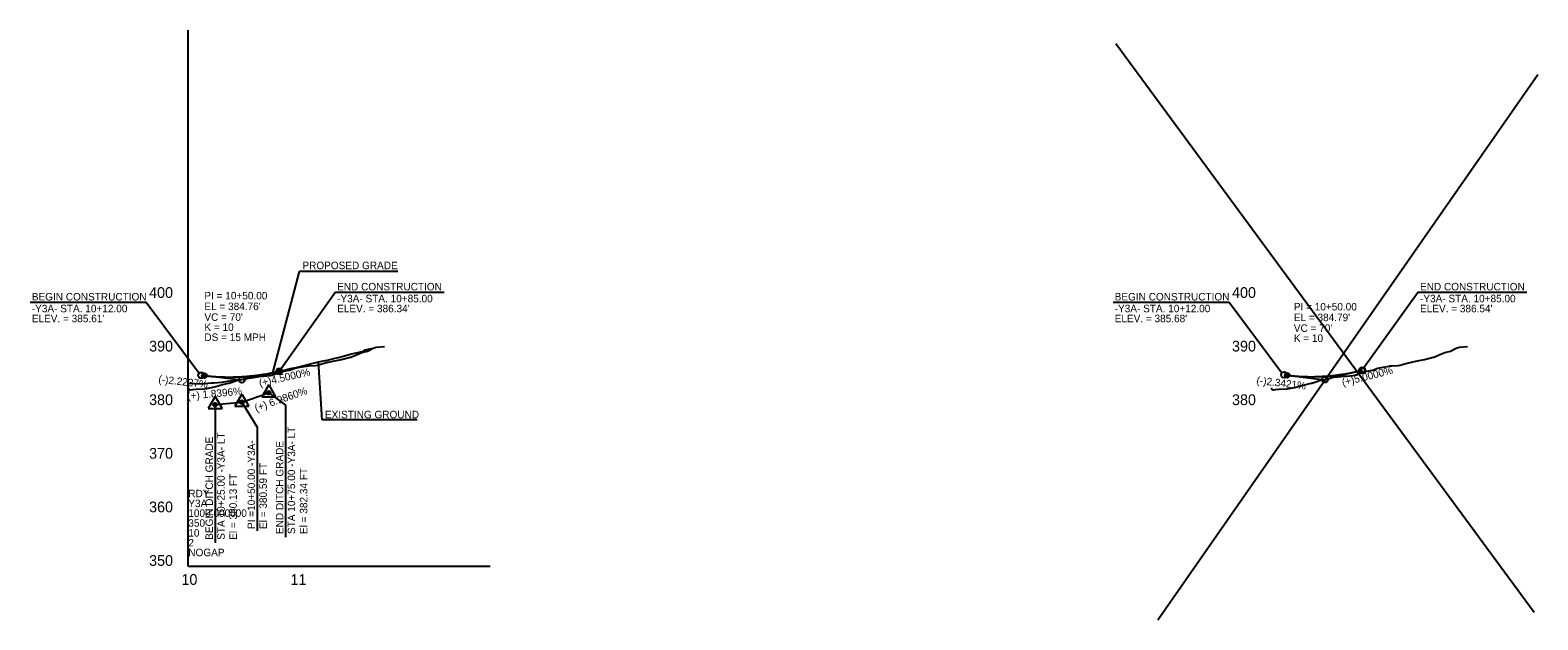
# Model space of a CAD drawing. Extents: x 1625686 to 1640492, y 1161393 to 1175642.
# Drawn here: x 1630069 to 1631477, y 1163675 to 1164225 of the extents above; entities that cross this region are included whole.
import ezdxf

# ---------------------------------------------------------------- set-up
doc = ezdxf.new("R2010")
doc.units = 0
for name, color, linetype in [('Exist Profile Cell', 7, 'Continuous'), ('Exist Vertical Profile Ground Line', 7, 'Continuous'), ('Exist Vertical Profile Horizontal Axis Label Major', 7, 'Continuous'), ('Exist Vertical Profile Vertical Axis Label', 7, 'Continuous'), ('Prop Vertical Profile Curve Label', 7, 'Continuous'), ('Prop Vertical Profile Ditch Grade Left', 7, 'Continuous'), ('Prop Vertical Profile Ditch Grade Left Label', 7, 'Continuous'), ('Prop Vertical Profile Grade', 7, 'Continuous'), ('Prop Vertical Profile Grade Label', 7, 'Continuous'), ('Prop VPI Ditch Grade Left Label', 7, 'Continuous'), ('Prop VPI Label', 7, 'Continuous'), ('Scratch_Level_1', 7, 'Continuous'), ('Scratch_Level_3', 7, 'Continuous')]:
    doc.layers.add(name, color=color, linetype=linetype)

msp = doc.modelspace()

# ---------------------------------------------------------------- linework, layer by layer
at = {"layer": 'Exist Profile Cell'}
for q in [(1630217, 1164224.9), (1630498.6, 1163724.9), (1630217, 1163724.9)]:
    msp.add_line((1630217, 1163724.9), q, dxfattribs=at)
at = {"layer": 'Exist Vertical Profile Ground Line'}
for points in [[(1630217, 1163895.6), (1630228, 1163894.9), (1630238.6, 1163895.8), (1630240.9, 1163895.9), (1630248.5, 1163896.4), (1630253.5, 1163897.3), (1630265.9, 1163899.1), (1630277.8, 1163900.9), (1630281.5, 1163901.5), (1630282.8, 1163901.8), (1630287.5, 1163902.9), (1630300.4, 1163906.2), (1630312.4, 1163909.1), (1630317.8, 1163910.3), (1630320.3, 1163910.9), (1630338.6, 1163915.5), (1630344.8, 1163916.6), (1630345.9, 1163916.7), (1630347.7, 1163917.2), (1630355.4, 1163919.2), (1630357.3, 1163919.6), (1630369.4, 1163922.8), (1630378, 1163924.9), (1630380.5, 1163925.5), (1630382.2, 1163926.6), (1630389.5, 1163928.1), (1630392.3, 1163929), (1630400.2, 1163929.7)], [(1631227.8, 1163891.3), (1631229, 1163889.4), (1631229.8, 1163889.3), (1631231.9, 1163889.7), (1631234.8, 1163890.1), (1631243, 1163890.4), (1631249.4, 1163891.6), (1631254.6, 1163892.8), (1631257.5, 1163893.7), (1631265, 1163895.6), (1631265.6, 1163895.7), (1631267.7, 1163896.3), (1631273.7, 1163898.3), (1631275.4, 1163898.3), (1631281.8, 1163899.8), (1631285.8, 1163901.2), (1631289.9, 1163901.6), (1631296.2, 1163902.1), (1631298, 1163902.1), (1631304, 1163902.8), (1631306.1, 1163903), (1631306.6, 1163903.2), (1631314.2, 1163905.7), (1631317, 1163906.7), (1631322.2, 1163907.8), (1631327.4, 1163909.5), (1631330.3, 1163910.1), (1631337.8, 1163911.5), (1631338.4, 1163911.6), (1631340.4, 1163911.7), (1631346.5, 1163912.1), (1631348.3, 1163912.5), (1631354.6, 1163914.3), (1631358.7, 1163915), (1631362.7, 1163916.1), (1631369.1, 1163917.4), (1631370.8, 1163917.6), (1631376.7, 1163919.1), (1631378.9, 1163919.7), (1631379.5, 1163919.9), (1631386.9, 1163923), (1631389.9, 1163924.1), (1631395, 1163925.5), (1631400.3, 1163928.1), (1631403.1, 1163929), (1631410.9, 1163929.7)]]:
    msp.add_lwpolyline(points, dxfattribs=at)
at = {"layer": 'Prop Vertical Profile Curve Label'}
for centre in [(1630302, 1163906.6), (1631312.8, 1163907.6), (1630232, 1163902.6), (1631242.8, 1163902.9)]:
    msp.add_circle(centre, 2.25, dxfattribs=at)
at = {"layer": 'Prop Vertical Profile Ditch Grade Left'}
msp.add_lwpolyline([(1630242, 1163875.5), (1630267, 1163877.8), (1630292, 1163886.6)], dxfattribs=at)
at = {"layer": 'Prop Vertical Profile Grade'}
for p, q in [((1630229, 1163902.9), (1630232, 1163902.6)), ((1631239.8, 1163903.3), (1631242.8, 1163902.9))]:
    msp.add_line(p, q, dxfattribs=at)
for points in [[(1630232, 1163902.6), (1630233.4, 1163902.4), (1630234.8, 1163902.3), (1630236.2, 1163902.2), (1630237.6, 1163902), (1630239, 1163901.9), (1630240.4, 1163901.8), (1630241.8, 1163901.7), (1630243.2, 1163901.6), (1630244.6, 1163901.6), (1630246, 1163901.5), (1630247.4, 1163901.5), (1630248.8, 1163901.4), (1630250.2, 1163901.4), (1630251.6, 1163901.3), (1630253, 1163901.3), (1630254.4, 1163901.3), (1630255.8, 1163901.3), (1630257.2, 1163901.3), (1630258.6, 1163901.3), (1630260, 1163901.4), (1630261.4, 1163901.4), (1630262.8, 1163901.4), (1630264.2, 1163901.5), (1630265.6, 1163901.6), (1630267, 1163901.6), (1630268.4, 1163901.7), (1630269.8, 1163901.8), (1630271.2, 1163901.9), (1630272.6, 1163902), (1630274, 1163902.2), (1630275.4, 1163902.3), (1630276.8, 1163902.4), (1630278.2, 1163902.6), (1630279.6, 1163902.7), (1630281, 1163902.9), (1630282.4, 1163903.1), (1630283.8, 1163903.3), (1630285.2, 1163903.5), (1630286.6, 1163903.7), (1630288, 1163903.9), (1630289.4, 1163904.1), (1630290.8, 1163904.4), (1630292.2, 1163904.6), (1630293.6, 1163904.9), (1630295, 1163905.1), (1630296.4, 1163905.4), (1630297.8, 1163905.7), (1630299.2, 1163906), (1630300.6, 1163906.3), (1630302, 1163906.6)], [(1631242.8, 1163902.9), (1631244.2, 1163902.8), (1631245.6, 1163902.6), (1631247, 1163902.5), (1631248.4, 1163902.4), (1631249.8, 1163902.2), (1631251.2, 1163902.1), (1631252.6, 1163902), (1631254, 1163901.9), (1631255.4, 1163901.9), (1631256.8, 1163901.8), (1631258.2, 1163901.7), (1631259.6, 1163901.7), (1631261, 1163901.7), (1631262.4, 1163901.6), (1631263.8, 1163901.6), (1631265.2, 1163901.6), (1631266.6, 1163901.6), (1631268, 1163901.6), (1631269.4, 1163901.7), (1631270.8, 1163901.7), (1631272.2, 1163901.7), (1631273.6, 1163901.8), (1631275, 1163901.9), (1631276.4, 1163902), (1631277.8, 1163902), (1631279.2, 1163902.1), (1631280.6, 1163902.2), (1631282, 1163902.4), (1631283.4, 1163902.5), (1631284.8, 1163902.6), (1631286.2, 1163902.8), (1631287.6, 1163902.9), (1631289, 1163903.1), (1631290.4, 1163903.3), (1631291.8, 1163903.5), (1631293.2, 1163903.7), (1631294.6, 1163903.9), (1631296, 1163904.1), (1631297.4, 1163904.3), (1631298.8, 1163904.6), (1631300.2, 1163904.8), (1631301.6, 1163905.1), (1631303, 1163905.4), (1631304.4, 1163905.7), (1631305.8, 1163906), (1631307.2, 1163906.3), (1631308.6, 1163906.6), (1631310, 1163906.9), (1631311.4, 1163907.2), (1631312.8, 1163907.6)]]:
    msp.add_spline(points, degree=3, dxfattribs=at)
at = {"layer": 'Prop Vertical Profile Grade Label'}
for p, q in [((1630296, 1163905.3), (1630320.8, 1163999.7)), ((1630412.7, 1163999.7), (1630320.8, 1163999.7)), ((1630354.3, 1163980.4), (1630302, 1163906.6)), ((1630354.3, 1163980.4), (1630455.7, 1163980.4)), ((1631365.1, 1163980.4), (1631314.2, 1163909.9)), ((1631365.1, 1163980.4), (1631466.5, 1163980.4)), ((1630069.4, 1163971), (1630177.8, 1163971)), ((1630177.8, 1163971), (1630227.2, 1163905)), ((1631080.2, 1163971), (1631188.6, 1163971)), ((1631188.6, 1163971), (1631237.8, 1163905.2))]:
    msp.add_line(p, q, dxfattribs=at)
at = {"layer": 'Prop VPI Ditch Grade Left Label'}
for p, q in [((1630292, 1163894), (1630285.5, 1163882.8)), ((1630292, 1163894), (1630298.5, 1163882.8)), ((1630242, 1163883), (1630235.5, 1163871.8)), ((1630242, 1163883), (1630248.5, 1163871.8)), ((1630267, 1163885.3), (1630260.5, 1163874.1)), ((1630267, 1163885.3), (1630273.5, 1163874.1)), ((1630285.5, 1163882.8), (1630298.5, 1163882.8)), ((1630235.5, 1163871.8), (1630248.5, 1163871.8)), ((1630242, 1163875.5), (1630242, 1163746.6)), ((1630242, 1163870.4), (1630242, 1163746.6)), ((1630260.5, 1163874.1), (1630273.5, 1163874.1))]:
    msp.add_line(p, q, dxfattribs=at)
for points in [[(1630292, 1163886.6), (1630307.7, 1163875.1), (1630307.7, 1163751.9)], [(1630267, 1163877.8), (1630281.3, 1163854.4), (1630281.3, 1163757.7)]]:
    msp.add_lwpolyline(points, dxfattribs=at)
for centre, radius in [((1630292, 1163886.6), 1.75), ((1630292, 1163886.6), 1.2), ((1630292, 1163886.6), 0.5), ((1630242, 1163875.5), 1.75), ((1630242, 1163875.5), 1.2), ((1630242, 1163875.5), 0.5), ((1630267, 1163877.8), 1.75), ((1630267, 1163877.8), 1.2), ((1630267, 1163877.8), 0.5)]:
    msp.add_circle(centre, radius, dxfattribs=at)
at = {"layer": 'Prop VPI Label'}
for p, q in [((1630342, 1163861.3), (1630338.6, 1163915.5)), ((1630232, 1163902.6), (1630264.2, 1163899)), ((1630302, 1163906.6), (1630269.7, 1163899.3)), ((1631242.8, 1163902.9), (1631275, 1163899.1)), ((1631312.8, 1163907.6), (1631280.4, 1163899.5)), ((1630430.6, 1163861.3), (1630342, 1163861.3))]:
    msp.add_line(p, q, dxfattribs=at)
for centre in [(1630302, 1163906.6), (1631312.8, 1163907.6), (1630229, 1163902.9), (1630267, 1163898.7), (1631239.8, 1163903.3), (1631277.8, 1163898.8)]:
    msp.add_circle(centre, 2.75, dxfattribs=at)
at = {"layer": 'Scratch_Level_1'}
msp.add_lwpolyline([(1630217, 1163891.3), (1630218.2, 1163889.4), (1630219, 1163889.3), (1630221.2, 1163889.7), (1630224.1, 1163890.1), (1630232.3, 1163890.4), (1630238.7, 1163891.6), (1630243.8, 1163892.8), (1630246.7, 1163893.7), (1630254.2, 1163895.6), (1630254.8, 1163895.7), (1630256.9, 1163896.3), (1630262.9, 1163898.3), (1630264.6, 1163898.3), (1630271, 1163899.8), (1630275, 1163901.2), (1630279.1, 1163901.6), (1630285.4, 1163902.1), (1630287.2, 1163902.1), (1630293.3, 1163902.8), (1630295.3, 1163903), (1630295.8, 1163903.2), (1630303.4, 1163905.7), (1630306.3, 1163906.7), (1630311.4, 1163907.8), (1630316.7, 1163909.5), (1630319.5, 1163910.1), (1630327.1, 1163911.5), (1630327.6, 1163911.6), (1630329.6, 1163911.7), (1630335.7, 1163912.1), (1630337.5, 1163912.5), (1630343.8, 1163914.3), (1630347.9, 1163915), (1630351.9, 1163916.1), (1630358.3, 1163917.4), (1630360, 1163917.6), (1630365.9, 1163919.1), (1630368.1, 1163919.7), (1630368.7, 1163919.9), (1630376.1, 1163923), (1630379.1, 1163924.1), (1630384.2, 1163925.5), (1630389.5, 1163928.1), (1630392.3, 1163929), (1630400.2, 1163929.7)], dxfattribs=at)
at = {"layer": 'Scratch_Level_3'}
for p, q in [((1631082.7, 1164212.3), (1631473.1, 1163681.9)), ((1631122.1, 1163674.8), (1631476.7, 1164183.6))]:
    msp.add_line(p, q, dxfattribs=at)

# ---------------------------------------------------------------- texts
at = {"layer": 'Exist Profile Cell'}
for s, p in [('RDY', (1630217, 1163789.1)), ('Y3A', (1630217, 1163779.9)), ('350', (1630217, 1163761.6)), ('1000.000000', (1630217, 1163770.8)), ('10', (1630217, 1163752.4)), ('2', (1630217, 1163743.2)), ('NOGAP', (1630217, 1163734.1))]:
    msp.add_text(s, height=7, dxfattribs=at).set_placement(p)
at = {"layer": 'Exist Vertical Profile Horizontal Axis Label Major'}
for s, p in [('10', (1630210.6, 1163707.4)), ('11', (1630312.4, 1163707.4))]:
    msp.add_text(s, height=10, dxfattribs=at).set_placement(p)
at = {"layer": 'Exist Vertical Profile Vertical Axis Label'}
for s, p in [('400', (1630180.4, 1163975.1)), ('400', (1631191.2, 1163975.1)), ('390', (1630180.4, 1163925.1)), ('390', (1631191.2, 1163925.1)), ('380', (1630180.4, 1163875.1)), ('380', (1631191.2, 1163875.1)), ('370', (1630180.4, 1163825.1)), ('360', (1630180.4, 1163775.1)), ('350', (1630180.4, 1163725.1))]:
    msp.add_text(s, height=10, dxfattribs=at).set_placement(p)
at = {"layer": 'Prop Vertical Profile Curve Label'}
for s, p in [("VC = 70'", (1630232, 1163953.7)), ('K = 10', (1630232, 1163944.3)), ("VC = 70'", (1631248.9, 1163943.4)), ('DS = 15 MPH', (1630232, 1163934.9)), ('K = 10', (1631248.9, 1163934))]:
    msp.add_text(s, height=7, dxfattribs=at).set_placement(p)
at = {"layer": 'Prop Vertical Profile Ditch Grade Left Label'}
for s, rotation, p in [('(+) 1.8396%', 5.2553, (1630216.3, 1163880.1)), ('(+) 6.9860%', 19.2543, (1630280.3, 1163868.8))]:
    msp.add_text(s, height=7, rotation=rotation, dxfattribs=at).set_placement(p)
at = {"layer": 'Prop Vertical Profile Grade Label'}
msp.add_text('PROPOSED GRADE', height=7, dxfattribs=at).set_placement((1630323.5, 1164001.9))
for s, rotation, p in [('(+)4.5000%', 12.6804, (1630283.8, 1163892.2)), ('(+)5.0000%', 14.0362, (1631294.7, 1163892.7)), ('(-)2.2237%', 353.6557, (1630188.8, 1163896)), ('(-)2.3421%', 353.3208, (1631213.8, 1163894.9))]:
    msp.add_text(s, height=7, rotation=rotation, dxfattribs=at).set_placement(p)
at = {"layer": 'Prop VPI Ditch Grade Left Label'}
for s, p in [('STA 10+75.00 -Y3A- LT', (1630316.7, 1163754.8)), ('BEGIN DITCH GRADE', (1630240, 1163749.4)), ('BEGIN DITCH GRADE', (1630240, 1163749.4)), ('STA 10+25.00 -Y3A- LT', (1630251, 1163749.4)), ('PI =10+50.00 -Y3A-', (1630279.3, 1163759.5)), ('END DITCH GRADE', (1630305.7, 1163754.8)), ('El = 380.13 FT', (1630262.3, 1163749.4)), ('El = 380.59 FT', (1630290.3, 1163759.5)), ('El = 382.34 FT', (1630328.1, 1163754.8))]:
    msp.add_text(s, height=7, rotation=90, dxfattribs=at).set_placement(p)
at = {"layer": 'Prop VPI Label'}
for s, p in [('BEGIN CONSTRUCTION', (1630070.9, 1163972.7)), ('PI = 10+50.00', (1630232, 1163973.7)), ('END CONSTRUCTION', (1630355.9, 1163982.1)), ('BEGIN CONSTRUCTION', (1631081.7, 1163972.7)), ('END CONSTRUCTION', (1631366.7, 1163982.1)), ('-Y3A- STA. 10+12.00', (1630070.9, 1163961.7)), ("EL = 384.76'", (1630232, 1163963.7)), ('-Y3A- STA. 10+85.00', (1630355.9, 1163971)), ("ELEV. = 386.34'", (1630355.9, 1163961.7)), ('-Y3A- STA. 10+12.00', (1631081.7, 1163961.7)), ('PI = 10+50.00', (1631248.9, 1163963.4)), ('-Y3A- STA. 10+85.00', (1631366.7, 1163971)), ("ELEV. = 386.54'", (1631366.7, 1163961.7)), ("ELEV. = 385.61'", (1630070.9, 1163952.4)), ("ELEV. = 385.68'", (1631081.7, 1163952.4)), ("EL = 384.79'", (1631248.9, 1163953.4)), ('EXISTING GROUND', (1630344.5, 1163862.8))]:
    msp.add_text(s, height=7, dxfattribs=at).set_placement(p)

doc.saveas('drawing.dxf')
